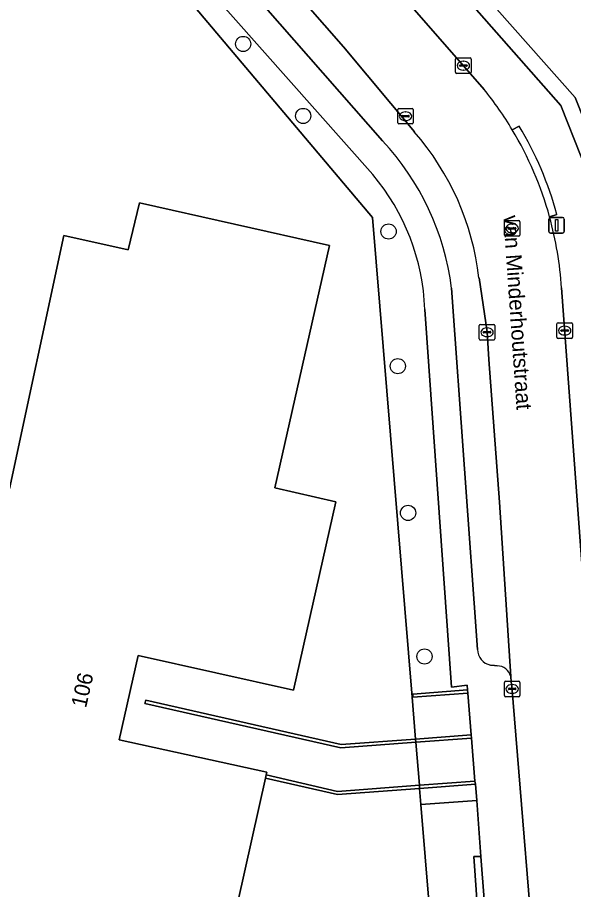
# Model space of a CAD drawing. Extents: x 162172 to 163187, y 382874 to 383685.
# Drawn here: x 162686.9 to 162722.7, y 383183.2 to 383239.4 of the extents above; entities that cross this region are included whole.
import ezdxf

# ---------------------------------------------------------------- set-up
doc = ezdxf.new("R2010")
doc.units = 0
for name, color, linetype in [('IMGEO_Berm_groen', 7, 'Continuous'), ('IMGEO_Boom', 7, 'Continuous'), ('IMGEO_Erf', 7, 'Continuous'), ('IMGEO_Groenvoorziening', 7, 'Continuous'), ('IMGEO_Hek', 7, 'Continuous'), ('IMGEO_Kolk', 7, 'Continuous'), ('IMGEO_Lichtmast', 7, 'Continuous'), ('IMGEO_Muur', 7, 'Continuous'), ('IMGEO_Openbare_ruimte_label', 7, 'Continuous'), ('IMGEO_Pand', 7, 'Continuous'), ('IMGEO_Pand_nummerreeks', 7, 'Continuous'), ('IMGEO_Parkeervlak_open', 7, 'Continuous'), ('IMGEO_Rijbaan_lokaal_open', 7, 'Continuous'), ('IMGEO_Rioolput', 7, 'Continuous'), ('IMGEO_Voetpad_open', 7, 'Continuous')]:
    doc.layers.add(name, color=color, linetype=linetype)

msp = doc.modelspace()

# ---------------------------------------------------------------- linework, layer by layer
at = {"layer": 'IMGEO_Berm_groen'}
msp.add_lwpolyline([(162716.279, 383185.309), (162716.729, 383185.316), (162716.471, 383188.924), (162712.883, 383188.659), (162714.318, 383171.307), (162717.264, 383171.207)], close=True, dxfattribs=at)
at = {"layer": 'IMGEO_Boom'}
for centre in [(162701.437, 383237.659), (162705.298, 383233.023), (162710.796, 383225.578), (162711.39, 383216.905), (162712.052, 383207.451), (162713.11, 383198.203)]:
    msp.add_circle(centre, 0.489, dxfattribs=at)
at = {"layer": 'IMGEO_Erf'}
for points in [[(162727.199, 383204.58), (162726.676, 383212.062), (162726.153, 383219.543), (162725.62, 383227.164), (162724.451, 383230.18), (162724.004, 383231.193), (162722.801, 383234.212), (162717.776, 383239.899), (162712.863, 383245.459), (162708.85, 383250), (162707.95, 383251.019), (162702.924, 383256.706), (162702.201, 383256.07), (162707.542, 383250), (162721.894, 383233.691), (162724.508, 383227.08), (162724.683, 383225.868), (162726.951, 383195.201), (162727.343, 383189.418), (162728.254, 383189.48), (162727.722, 383197.098)], [(162712.883, 383188.659), (162712.796, 383189.705), (162707.504, 383189.315), (162702.876, 383190.365), (162699.343, 383174.603), (162714.318, 383171.307)]]:
    msp.add_lwpolyline(points, close=True, dxfattribs=at)
msp.add_lwpolyline([(162686.39, 383208.994), (162689.896, 383225.323), (162694.037, 383224.407), (162694.755, 383227.42), (162706.999, 383224.669), (162703.484, 383209.059), (162707.405, 383208.175), (162704.673, 383196.025), (162694.672, 383198.273), (162693.448, 383192.829), (162702.962, 383190.749), (162702.926, 383190.59), (162707.515, 383189.513), (162712.779, 383189.911), (162712.55, 383192.673), (162707.728, 383192.311), (162695.111, 383195.165), (162695.161, 383195.389), (162707.748, 383192.524), (162712.533, 383192.884), (162712.311, 383195.573), (162709.753, 383226.486), (162692.642, 383246.796), (162622.24, 383184.334)], dxfattribs=at)
at = {"layer": 'IMGEO_Groenvoorziening'}
for points in [[(162689.625, 383250.21), (162689.305, 383250), (162664.293, 383227.801), (162660.781, 383224.678), (162625.12, 383192.791), (162627.743, 383189.782), (162624.342, 383186.791), (162621.746, 383189.775), (162621.727, 383189.758), (162619.551, 383187.812), (162618.811, 383184.628), (162656.37, 383176.3), (162664.103, 383174.592), (162683.655, 383170.289), (162683.702, 383170.501), (162622.24, 383184.334), (162692.642, 383246.796), (162709.753, 383226.486), (162712.311, 383195.573)], [(162709.774, 383229.25), (162691.638, 383249.728)], [(162712.311, 383195.573), (162712.365, 383195.577), (162712.354, 383195.785), (162715.885, 383196.064), (162715.861, 383196.364), (162714.85, 383196.217), (162713.132, 383220.561)]]:
    msp.add_lwpolyline(points, dxfattribs=at)
msp.add_lwpolyline([(162716.729, 383185.316), (162716.279, 383185.309), (162717.264, 383171.207), (162717.838, 383171.191)], close=True, dxfattribs=at)
msp.add_arc((162698.832, 383220.028), 14.309, 2.1343, 40.1253, dxfattribs=at)
at = {"layer": 'IMGEO_Hek'}
for points in [[(162683.702, 383170.501), (162622.24, 383184.334), (162692.642, 383246.796), (162709.753, 383226.486), (162712.533, 383192.884)], [(162712.55, 383192.673), (162712.779, 383189.911)], [(162712.796, 383189.705), (162712.883, 383188.659), (162714.318, 383171.307)]]:
    msp.add_lwpolyline(points, dxfattribs=at)
at = {"layer": 'IMGEO_Kolk'}
for p, q in [((162715.112, 383235.835), (162715.112, 383236.687)), ((162715.187, 383236.761), (162716.039, 383236.761)), ((162715.6, 383236.541), (162715.625, 383236.541)), ((162716.113, 383236.687), (162716.113, 383235.835)), ((162715.371, 383236.255), (162715.371, 383236.267)), ((162715.809, 383236.218), (162715.411, 383236.218)), ((162715.414, 383236.304), (162715.812, 383236.304)), ((162715.623, 383235.981), (162715.598, 383235.981)), ((162715.855, 383236.267), (162715.855, 383236.255)), ((162716.039, 383235.761), (162715.187, 383235.761)), ((162711.388, 383232.578), (162711.388, 383233.43)), ((162711.463, 383233.504), (162712.315, 383233.504)), ((162711.69, 383233.047), (162712.088, 383233.047)), ((162711.876, 383233.284), (162711.901, 383233.284)), ((162712.389, 383233.43), (162712.389, 383232.578)), ((162712.315, 383232.504), (162711.463, 383232.504)), ((162711.647, 383232.998), (162711.647, 383233.01)), ((162712.085, 383232.961), (162711.687, 383232.961)), ((162711.899, 383232.724), (162711.874, 383232.724)), ((162712.131, 383233.01), (162712.131, 383232.998)), ((162716.712, 383219.589), (162717.564, 383219.589)), ((162721.637, 383218.769), (162721.637, 383219.621)), ((162721.712, 383219.695), (162722.564, 383219.695)), ((162722.638, 383219.621), (162722.638, 383218.769)), ((162716.637, 383218.663), (162716.637, 383219.515)), ((162716.896, 383219.083), (162716.896, 383219.095)), ((162717.334, 383219.046), (162716.936, 383219.046)), ((162716.939, 383219.132), (162717.337, 383219.132)), ((162717.125, 383219.369), (162717.15, 383219.369)), ((162717.38, 383219.095), (162717.38, 383219.083)), ((162717.638, 383219.515), (162717.638, 383218.663)), ((162721.896, 383219.189), (162721.896, 383219.201)), ((162722.334, 383219.152), (162721.936, 383219.152)), ((162721.939, 383219.238), (162722.337, 383219.238)), ((162722.125, 383219.475), (162722.15, 383219.475)), ((162722.38, 383219.201), (162722.38, 383219.189)), ((162717.564, 383218.589), (162716.712, 383218.589)), ((162717.148, 383218.809), (162717.123, 383218.809)), ((162722.564, 383218.695), (162721.712, 383218.695)), ((162722.148, 383218.915), (162722.123, 383218.915)), ((162718.249, 383195.685), (162718.249, 383196.537)), ((162718.324, 383196.611), (162719.176, 383196.611)), ((162719.25, 383196.537), (162719.25, 383195.685)), ((162718.508, 383196.105), (162718.508, 383196.117)), ((162718.946, 383196.068), (162718.548, 383196.068)), ((162718.551, 383196.154), (162718.949, 383196.154)), ((162718.737, 383196.391), (162718.762, 383196.391)), ((162718.992, 383196.117), (162718.992, 383196.105)), ((162719.176, 383195.611), (162718.324, 383195.611)), ((162718.76, 383195.831), (162718.735, 383195.831))]:
    msp.add_line(p, q, dxfattribs=at)
for points in [[(162715.112, 383235.835), (162715.112, 383236.687)], [(162715.187, 383236.761), (162716.039, 383236.761)], [(162716.113, 383236.687), (162716.113, 383235.835)], [(162716.039, 383235.761), (162715.187, 383235.761)], [(162711.388, 383232.578), (162711.388, 383233.43)], [(162711.463, 383233.504), (162712.315, 383233.504)], [(162712.389, 383233.43), (162712.389, 383232.578)], [(162712.315, 383232.504), (162711.463, 383232.504)], [(162716.712, 383219.589), (162717.564, 383219.589)], [(162721.637, 383218.769), (162721.637, 383219.621)], [(162721.712, 383219.695), (162722.564, 383219.695)], [(162722.638, 383219.621), (162722.638, 383218.769)], [(162716.637, 383218.663), (162716.637, 383219.515)], [(162717.638, 383219.515), (162717.638, 383218.663)], [(162717.564, 383218.589), (162716.712, 383218.589)], [(162722.564, 383218.695), (162721.712, 383218.695)], [(162718.249, 383195.685), (162718.249, 383196.537)], [(162718.324, 383196.611), (162719.176, 383196.611)], [(162719.25, 383196.537), (162719.25, 383195.685)], [(162719.176, 383195.611), (162718.324, 383195.611)]]:
    msp.add_lwpolyline(points, dxfattribs=at)
for centre, radius, start, end in [((162715.189, 383236.685), 0.0765, 91.552, 178.448), ((162715.189, 383236.685), 0.0765, 91.552, 178.448), ((162716.037, 383236.685), 0.0765, 1.552, 88.448), ((162716.037, 383236.685), 0.0765, 1.552, 88.448), ((162715.189, 383235.837), 0.0765, 181.552, 268.448), ((162715.189, 383235.837), 0.0765, 181.552, 268.448), ((162715.411, 383236.264), 0.0403, 85.8775, 175.7526), ((162715.408, 383236.254), 0.0366, 178.938, 274.7102), ((162715.812, 383236.261), 0.043, 264.8664, 352.4533), ((162715.816, 383236.266), 0.0386, 1.7309, 96.639), ((162716.037, 383235.837), 0.0765, 271.552, 358.448), ((162716.037, 383235.837), 0.0765, 271.552, 358.448), ((162711.465, 383233.428), 0.0765, 91.552, 178.448), ((162711.465, 383233.428), 0.0765, 91.552, 178.448), ((162711.687, 383233.007), 0.0403, 85.8775, 175.7526), ((162712.092, 383233.009), 0.0386, 1.7309, 96.639), ((162712.313, 383233.428), 0.0765, 1.552, 88.448), ((162712.313, 383233.428), 0.0765, 1.552, 88.448), ((162711.465, 383232.58), 0.0765, 181.552, 268.448), ((162711.465, 383232.58), 0.0765, 181.552, 268.448), ((162711.684, 383232.997), 0.0366, 178.938, 274.7102), ((162712.088, 383233.004), 0.043, 264.8664, 352.4533), ((162712.313, 383232.58), 0.0765, 271.552, 358.448), ((162712.313, 383232.58), 0.0765, 271.552, 358.448), ((162716.714, 383219.513), 0.0765, 91.552, 178.448), ((162716.714, 383219.513), 0.0765, 91.552, 178.448), ((162717.562, 383219.513), 0.0765, 1.552, 88.448), ((162717.562, 383219.513), 0.0765, 1.552, 88.448), ((162721.714, 383219.619), 0.0765, 91.552, 178.448), ((162721.714, 383219.619), 0.0765, 91.552, 178.448), ((162722.562, 383219.619), 0.0765, 1.552, 88.448), ((162722.562, 383219.619), 0.0765, 1.552, 88.448), ((162716.936, 383219.092), 0.0403, 85.8775, 175.7526), ((162716.933, 383219.082), 0.0366, 178.938, 274.7102), ((162717.337, 383219.089), 0.043, 264.8664, 352.4533), ((162717.341, 383219.094), 0.0386, 1.7309, 96.639), ((162721.936, 383219.198), 0.0403, 85.8775, 175.7526), ((162721.933, 383219.188), 0.0366, 178.938, 274.7102), ((162722.337, 383219.195), 0.043, 264.8664, 352.4533), ((162722.341, 383219.2), 0.0386, 1.7309, 96.639), ((162716.714, 383218.665), 0.0765, 181.552, 268.448), ((162716.714, 383218.665), 0.0765, 181.552, 268.448), ((162717.562, 383218.665), 0.0765, 271.552, 358.448), ((162717.562, 383218.665), 0.0765, 271.552, 358.448), ((162721.714, 383218.771), 0.0765, 181.552, 268.448), ((162721.714, 383218.771), 0.0765, 181.552, 268.448), ((162722.562, 383218.771), 0.0765, 271.552, 358.448), ((162722.562, 383218.771), 0.0765, 271.552, 358.448), ((162718.326, 383196.535), 0.0765, 91.552, 178.448), ((162718.326, 383196.535), 0.0765, 91.552, 178.448), ((162719.174, 383196.535), 0.0765, 1.552, 88.448), ((162719.174, 383196.535), 0.0765, 1.552, 88.448), ((162718.548, 383196.114), 0.0403, 85.8775, 175.7526), ((162718.545, 383196.104), 0.0366, 178.938, 274.7102), ((162718.949, 383196.111), 0.043, 264.8664, 352.4533), ((162718.953, 383196.116), 0.0386, 1.7309, 96.639), ((162718.326, 383195.687), 0.0765, 181.552, 268.448), ((162718.326, 383195.687), 0.0765, 181.552, 268.448), ((162719.174, 383195.687), 0.0765, 271.552, 358.448), ((162719.174, 383195.687), 0.0765, 271.552, 358.448)]:
    msp.add_arc(centre, radius, start, end, dxfattribs=at)
for centre, major_axis, ratio, start_param, end_param in [((162715.599, 383236.261), (-0.387, 0.002), 0.722429, 4.712389, 7.853982), ((162715.624, 383236.261), (-0.39, 0.002), 0.717154, 1.570796, 4.712389), ((162711.875, 383233.004), (-0.387, 0.002), 0.722429, 4.712389, 7.853982), ((162711.9, 383233.004), (-0.39, 0.002), 0.717154, 1.570796, 4.712389), ((162717.124, 383219.089), (-0.387, 0.002), 0.722429, 4.712389, 7.853982), ((162717.149, 383219.089), (-0.39, 0.002), 0.717154, 1.570796, 4.712389), ((162722.124, 383219.195), (-0.387, 0.002), 0.722429, 4.712389, 7.853982), ((162722.149, 383219.195), (-0.39, 0.002), 0.717154, 1.570796, 4.712389), ((162718.736, 383196.111), (-0.387, 0.002), 0.722429, 4.712389, 7.853982), ((162718.761, 383196.111), (-0.39, 0.002), 0.717154, 1.570796, 4.712389)]:
    msp.add_ellipse(centre, major_axis=major_axis, ratio=ratio, start_param=start_param, end_param=end_param, dxfattribs=at)
at = {"layer": 'IMGEO_Lichtmast'}
for p, q in [((162721.114, 383225.578), (162721.114, 383226.378)), ((162721.114, 383226.378), (162721.114, 383225.578)), ((162721.214, 383226.478), (162722.004, 383226.478)), ((162722.004, 383226.478), (162721.214, 383226.478)), ((162722.104, 383226.378), (162722.104, 383225.578)), ((162722.104, 383225.578), (162722.104, 383226.378)), ((162722.004, 383225.478), (162721.214, 383225.478)), ((162721.214, 383225.478), (162722.004, 383225.478))]:
    msp.add_line(p, q, dxfattribs=at)
msp.add_lwpolyline([(162721.534, 383226.353), (162721.684, 383226.353), (162721.684, 383225.603), (162721.534, 383225.603), (162721.534, 383226.353)], dxfattribs=at)
for centre, start, end in [((162721.214, 383226.378), 90, 180), ((162721.214, 383226.378), 90, 180), ((162722.004, 383226.378), 0, 90), ((162722.004, 383226.378), 360, 90), ((162721.214, 383225.578), 180, 270), ((162721.214, 383225.578), 180, 270), ((162722.004, 383225.578), 270, 0), ((162722.004, 383225.578), 270, 0)]:
    msp.add_arc(centre, 0.1, start, end, dxfattribs=at)
at = {"layer": 'IMGEO_Muur'}
for points in [[(162715.885, 383196.064), (162712.354, 383195.785), (162712.365, 383195.577), (162715.902, 383195.847)], [(162712.55, 383192.673), (162712.533, 383192.884), (162707.748, 383192.524), (162695.161, 383195.389), (162695.111, 383195.165), (162707.728, 383192.311)], [(162716.113, 383193.154), (162712.533, 383192.884), (162712.55, 383192.673), (162716.13, 383192.941)], [(162702.876, 383190.365), (162707.504, 383189.315), (162712.796, 383189.705), (162712.779, 383189.911), (162707.515, 383189.513), (162702.926, 383190.59)], [(162716.347, 383190.18), (162712.779, 383189.911), (162712.796, 383189.705), (162716.396, 383189.971)]]:
    msp.add_lwpolyline(points, close=True, dxfattribs=at)
at = {"layer": 'IMGEO_Pand'}
msp.add_lwpolyline([(162717.776, 383239.899), (162722.801, 383234.212), (162724.004, 383231.193), (162728.649, 383233.044), (162732.427, 383234.55), (162730.45, 383239.512), (162727.901, 383238.496), (162722.771, 383244.312)], close=True, dxfattribs=at)
msp.add_lwpolyline([(162699.343, 383174.603), (162702.876, 383190.365), (162702.926, 383190.59), (162702.962, 383190.749), (162693.448, 383192.829), (162694.672, 383198.273), (162704.673, 383196.025), (162707.405, 383208.175), (162703.484, 383209.059), (162706.999, 383224.669), (162694.755, 383227.42), (162694.037, 383224.407), (162689.896, 383225.323), (162686.39, 383208.994)], dxfattribs=at)
at = {"layer": 'IMGEO_Parkeervlak_open'}
for points in [[(162712.455, 383231.997), (162707.887, 383237.47), (162699.636, 383246.915), (162697.98, 383248.788)], [(162698.102, 383245.467), (162710.399, 383231.427)], [(162717.931, 383208.143), (162717.258, 383217.338), (162717.135, 383219.11), (162716.618, 383222.588)], [(162714.847, 383221.932), (162716.525, 383198.649)], [(162718.659, 383196.919), (162717.931, 383208.143)], [(162717.349, 383197.648), (162717.609, 383197.615), (162717.785, 383197.603)]]:
    msp.add_lwpolyline(points, dxfattribs=at)
for centre, radius, start, end in [((162699.344, 383220.571), 17.391, 6.661, 41.0728), ((162698.032, 383219.844), 16.945, 7.0781, 43.124), ((162717.583, 383198.68), 1.059, 181.7019, 257.219), ((162717.773, 383196.687), 0.916, 14.6595, 89.2464)]:
    msp.add_arc(centre, radius, start, end, dxfattribs=at)
at = {"layer": 'IMGEO_Rijbaan_lokaal_open'}
for points in [[(162703.606, 383250), (162700.253, 383253.528), (162698.395, 383255.671), (162697.939, 383256.199), (162694.32, 383252.709), (162696.466, 383250.295), (162697.98, 383248.788), (162699.636, 383246.915), (162707.887, 383237.47), (162712.455, 383231.997)], [(162716.95, 383234.725), (162709.168, 383243.653), (162703.606, 383250)], [(162716.618, 383222.588), (162717.135, 383219.11), (162717.258, 383217.338), (162717.931, 383208.143), (162718.659, 383196.919), (162718.681, 383196.574), (162718.735, 383196.282), (162720.508, 383174.468)], [(162720.332, 383171.339), (162719.685, 383168.388), (162717.621, 383158.967), (162716.16, 383152.285), (162715.139, 383147.923), (162721.042, 383146.61), (162724.159, 383160.942), (162725.521, 383167.025), (162725.709, 383167.926), (162725.753, 383169.405), (162725.756, 383169.512), (162725.711, 383170.959), (162725.556, 383173.167), (162724.694, 383183.415), (162724.622, 383184.384), (162724.379, 383187.917), (162723.663, 383198.352), (162721.935, 383221.945)]]:
    msp.add_lwpolyline(points, dxfattribs=at)
for centre, radius, start, end in [((162698.901, 383220.19), 23.173, 31.0327, 38.8443), ((162699.344, 383220.571), 17.391, 6.661, 41.0728), ((162699.033, 383220.363), 22.972, 15.5316, 30.8336), ((162699.206, 383220.469), 22.776, 3.7161, 15.3916)]:
    msp.add_arc(centre, radius, start, end, dxfattribs=at)
at = {"layer": 'IMGEO_Rioolput'}
for p, q in [((162718.33, 383226.278), (162719.182, 383226.278)), ((162718.255, 383225.352), (162718.255, 383226.204)), ((162718.514, 383225.772), (162718.514, 383225.784)), ((162718.952, 383225.735), (162718.554, 383225.735)), ((162718.557, 383225.821), (162718.955, 383225.821)), ((162718.743, 383226.058), (162718.768, 383226.058)), ((162718.998, 383225.784), (162718.998, 383225.772)), ((162719.256, 383226.204), (162719.256, 383225.352)), ((162719.182, 383225.278), (162718.33, 383225.278)), ((162718.766, 383225.498), (162718.741, 383225.498))]:
    msp.add_line(p, q, dxfattribs=at)
for points in [[(162718.33, 383226.278), (162719.182, 383226.278)], [(162718.255, 383225.352), (162718.255, 383226.204)], [(162719.256, 383226.204), (162719.256, 383225.352)], [(162719.182, 383225.278), (162718.33, 383225.278)]]:
    msp.add_lwpolyline(points, dxfattribs=at)
for centre, radius, start, end in [((162718.332, 383226.202), 0.0765, 91.552, 178.448), ((162718.332, 383226.202), 0.0765, 91.552, 178.448), ((162719.18, 383226.202), 0.0765, 1.552, 88.448), ((162719.18, 383226.202), 0.0765, 1.552, 88.448), ((162718.554, 383225.781), 0.0403, 85.8775, 175.7526), ((162718.551, 383225.771), 0.0366, 178.938, 274.7102), ((162718.955, 383225.778), 0.043, 264.8664, 352.4533), ((162718.959, 383225.783), 0.0386, 1.7309, 96.639), ((162718.332, 383225.354), 0.0765, 181.552, 268.448), ((162718.332, 383225.354), 0.0765, 181.552, 268.448), ((162719.18, 383225.354), 0.0765, 271.552, 358.448), ((162719.18, 383225.354), 0.0765, 271.552, 358.448)]:
    msp.add_arc(centre, radius, start, end, dxfattribs=at)
for centre, major_axis, ratio, start_param, end_param in [((162718.742, 383225.778), (-0.387, 0.002), 0.722429, 4.712389, 7.853982), ((162718.767, 383225.778), (-0.39, 0.002), 0.717154, 1.570796, 4.712389)]:
    msp.add_ellipse(centre, major_axis=major_axis, ratio=ratio, start_param=start_param, end_param=end_param, dxfattribs=at)
at = {"layer": 'IMGEO_Voetpad_open'}
for points in [[(162724.683, 383225.868), (162724.508, 383227.08), (162721.894, 383233.691), (162707.542, 383250), (162702.201, 383256.07), (162699.476, 383259.167), (162697.939, 383256.199), (162698.395, 383255.671), (162700.253, 383253.528), (162703.606, 383250), (162709.168, 383243.653), (162716.95, 383234.725)], [(162697.98, 383248.788), (162696.466, 383250.295), (162694.32, 383252.709), (162691.638, 383249.728), (162709.774, 383229.25)], [(162710.399, 383231.427), (162698.102, 383245.467)], [(162719.198, 383232.366), (162718.758, 383232.137)], [(162718.758, 383232.137), (162719.198, 383232.366)], [(162721.166, 383226.514), (162721.631, 383226.682)], [(162721.631, 383226.682), (162721.166, 383226.514)], [(162721.935, 383221.945), (162723.663, 383198.352), (162724.379, 383187.917), (162724.877, 383187.961), (162725.192, 383183.459), (162724.694, 383183.415), (162725.556, 383173.167), (162728.442, 383173.18), (162727.457, 383187.732), (162727.343, 383189.418), (162726.951, 383195.201), (162724.683, 383225.868)], [(162716.525, 383198.649), (162714.847, 383221.932)], [(162713.132, 383220.561), (162714.85, 383196.217), (162715.861, 383196.364), (162715.885, 383196.064), (162715.902, 383195.847), (162716.113, 383193.154), (162716.13, 383192.941), (162716.347, 383190.18), (162716.396, 383189.971), (162716.471, 383188.924), (162716.729, 383185.316), (162717.838, 383171.191), (162720.332, 383171.339)], [(162717.785, 383197.603), (162717.609, 383197.615), (162717.349, 383197.648)], [(162718.735, 383196.282), (162718.681, 383196.574), (162718.659, 383196.919)], [(162720.508, 383174.468), (162718.735, 383196.282)]]:
    msp.add_lwpolyline(points, dxfattribs=at)
for points in [[(162715.902, 383195.847), (162712.365, 383195.577), (162712.311, 383195.573), (162712.533, 383192.884), (162716.113, 383193.154)], [(162716.13, 383192.941), (162712.55, 383192.673), (162712.779, 383189.911), (162716.347, 383190.18)], [(162716.396, 383189.971), (162712.796, 383189.705), (162712.883, 383188.659), (162716.471, 383188.924)]]:
    msp.add_lwpolyline(points, close=True, dxfattribs=at)
for centre, radius, start, end in [((162698.901, 383220.19), 23.173, 31.0327, 38.8443), ((162699.033, 383220.363), 22.972, 15.5316, 30.8336), ((162700.584, 383221.036), 21.791, 15.0172, 31.3289), ((162700.584, 383221.036), 21.791, 15.0172, 31.3289), ((162698.032, 383219.844), 16.945, 7.0781, 43.124), ((162698.832, 383220.028), 14.309, 2.1343, 40.1253), ((162699.206, 383220.469), 22.776, 3.7161, 15.3916), ((162717.583, 383198.68), 1.059, 181.7019, 257.219), ((162717.773, 383196.687), 0.916, 14.6595, 89.2464)]:
    msp.add_arc(centre, radius, start, end, dxfattribs=at)

# ---------------------------------------------------------------- texts
at = {"layer": 'IMGEO_Openbare_ruimte_label'}
msp.add_text('van Minderhoutstraat', height=1, rotation=273.955, dxfattribs=at).set_placement((162718.175, 383226.602))
msp.add_text('van Minderhoutstraat', height=1, rotation=273.955, dxfattribs=at).set_placement((162718.175, 383226.602))
at = {"layer": 'IMGEO_Pand_nummerreeks'}
msp.add_text('106', height=1, rotation=77.3264, dxfattribs=at).set_placement((162691.319, 383194.847))

doc.saveas('drawing.dxf')
